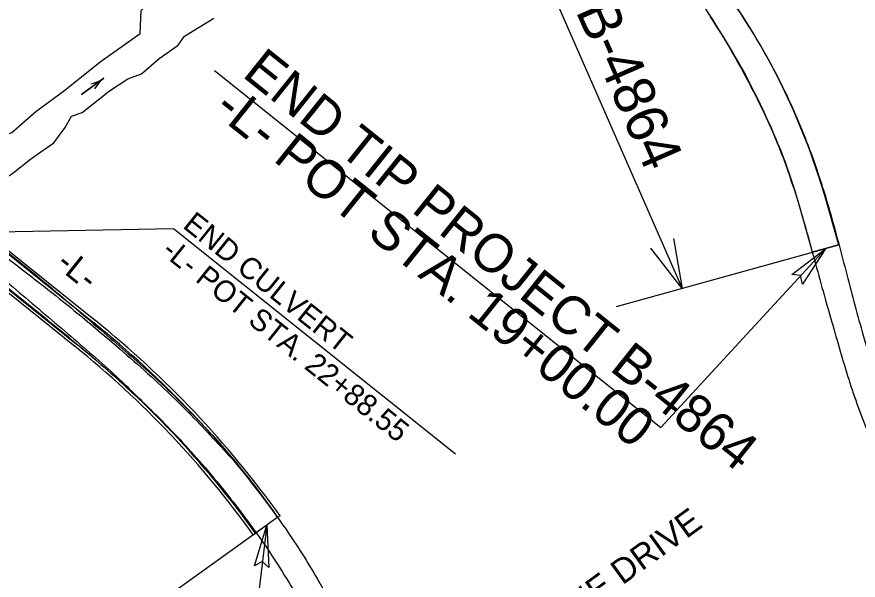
# Model space of a CAD drawing. Extents: x 1730256 to 1738218, y 910410 to 917906.
# Drawn here: x 1734907 to 1735520, y 915111 to 915523 of the extents above; entities that cross this region are included whole.
import ezdxf

# ---------------------------------------------------------------- set-up
doc = ezdxf.new("R2010")
doc.units = 0
for name, color, linetype in [('Default', 7, 'Continuous'), ('Old_Level_23', 7, 'Continuous'), ('Old_Level_3', 7, 'Continuous'), ('Old_Level_5', 7, 'Continuous'), ('Prop DSN Text', 7, 'Continuous'), ('Prop EOT', 7, 'Continuous'), ('Prop Paved Shoulder', 7, 'Continuous'), ('Prop Shade Light', 7, 'Continuous')]:
    doc.layers.add(name, color=color, linetype=linetype)

# ---------------------------------------------------------------- blocks, each defined once
blk = doc.blocks.new('EXIST HYDRO RIVER FLOW ARROW')
at = {"layer": 'Default'}
blk.add_line((0, 0), (0, 0), dxfattribs=at)
blk.add_lwpolyline([(0, 0.04575), (0.03775, 0.03), (0.07725, 0.01725), (0.118, 0.00775), (0.159, 0.0015), (0.2, 0), (-0.2, 0), (0.2, 0), (0.159, -0.0015), (0.118, -0.00775), (0.07725, -0.01725), (0.03775, -0.03), (0, -0.04575)], dxfattribs=at)

msp = doc.modelspace()

# ---------------------------------------------------------------- linework, layer by layer
at = {"layer": 'Old_Level_23'}
for p, q in [((1735146.86, 915884), (1735391.91, 915324.39)), ((1735496.49, 915353.46), (1735343.74, 915311)), ((1735088.89, 915151.46), (1734908.92, 915022.39)), ((1735088.89, 915151.46), (1735048.8, 914819.96))]:
    msp.add_line(p, q, dxfattribs=at)
at = {"layer": 'Old_Level_3'}
for points in [[(1735388.43, 915590.42), (1735416.78, 915551.19), (1735441.77, 915513.78), (1735465.3, 915471.57), (1735485.01, 915425.76), (1735499.55, 915381.43), (1735512.09, 915334.5), (1735524.18, 915290.01), (1735536.56, 915251.67), (1735553.3, 915211.16), (1735574.05, 915173.58), (1735599.55, 915136.89), (1735628.53, 915103.19), (1735661.79, 915070.16), (1735681.36, 915051.5)], [(1735374.46, 915580.41), (1735401.37, 915540.39), (1735425.26, 915502.31), (1735446.73, 915462.77), (1735465.76, 915420.2), (1735480.61, 915373.81), (1735493.26, 915327.98), (1735505.79, 915283.89), (1735518.61, 915242.74), (1735535.21, 915202.71), (1735557.35, 915162.87), (1735584.25, 915124.34), (1735613.79, 915089.74), (1735647.95, 915055.56), (1735667.73, 915036.98)], [(1734867.86, 915373.07), (1734891.7, 915356.76), (1734930.33, 915326.02), (1734970.32, 915291.99), (1735005.27, 915261.32), (1735024.06, 915243.43), (1735033.15, 915234.18), (1735042.14, 915224.81), (1735056.21, 915209.41), (1735069.65, 915193.46), (1735086.65, 915171.45), (1735102.74, 915148.77), (1735125.96, 915112.12), (1735140.95, 915084.89), (1735155.38, 915057.39), (1735158.12, 915051.66), (1735159.45, 915048.78), (1735160.89, 915045.93), (1735165.87, 915039.38), (1735172.8, 915033), (1735180.64, 915028.28), (1735182.57, 915027.8), (1735184.51, 915027.58), (1735188.38, 915027.7), (1735201.89, 915029.6), (1735214.29, 915032.53), (1735224.55, 915035.86)], [(1734867.91, 915371.3), (1734901.92, 915344.86), (1734933.09, 915320.66), (1734950.45, 915306.67), (1734981.89, 915280.2), (1735021.66, 915243.96), (1735053.56, 915211.01), (1735069.65, 915193.46)], [(1734867.91, 915371.3), (1734901.92, 915344.86), (1734933.09, 915320.66), (1734950.45, 915306.67), (1734981.89, 915280.2), (1735021.66, 915243.96), (1735053.56, 915211.01), (1735069.65, 915193.46)], [(1734858.22, 915360.67), (1734895.64, 915328.62), (1734934.22, 915297.2), (1734972.7, 915264.77), (1735005.94, 915234.2), (1735039.93, 915198.24), (1735072.41, 915158), (1735096.75, 915123.08), (1735121.96, 915080.08), (1735142.34, 915040.74), (1735163.87, 914992.3), (1735179.09, 914950.63), (1735193.56, 914895.57), (1735202.84, 914849.68), (1735206.11, 914828.68)], [(1734860.08, 915360.81), (1734901.23, 915327.52), (1734939.09, 915295.34), (1734975.42, 915263.7), (1735005.94, 915234.2)], [(1734860.08, 915360.81), (1734901.23, 915327.52), (1734939.09, 915295.34), (1734975.42, 915263.7), (1735005.94, 915234.2)]]:
    msp.add_spline(points, degree=3, dxfattribs=at)
at = {"layer": 'Old_Level_5'}
for points in [[(1734842.2, 915393.26), (1734849.26, 915399.96), (1734854.95, 915407.39), (1734872.33, 915423.08), (1734887.54, 915432.8), (1734903.06, 915438.24), (1734920.36, 915453.61), (1734941.62, 915469.24), (1734967.32, 915489.78), (1734996.6, 915510.63), (1734997.24, 915527.41), (1735007.05, 915536.59), (1735033.32, 915541.68)], [(1734864.64, 915375.65), (1734872.89, 915389.34), (1734877.09, 915389.68), (1734884.72, 915394.32), (1734889.7, 915399.34), (1734903.75, 915408.63), (1734916.66, 915418.71), (1734924.09, 915424.15), (1734933.66, 915430.75), (1734941.81, 915441.88), (1734946.57, 915450.27), (1734954.38, 915452.81), (1734974.19, 915468.68), (1734987.64, 915477.42), (1734997.51, 915481.05), (1735010.34, 915492.29), (1735024.21, 915501.95), (1735029.03, 915508.6), (1735050.33, 915521.75)]]:
    msp.add_lwpolyline(points, dxfattribs=at)
at = {"layer": 'Prop DSN Text'}
for p, q in [((1735050.76, 915483.64), (1735376.48, 915222.96)), ((1734865, 915365.22), (1735020.92, 915368.23)), ((1735020.92, 915368.23), (1735226.7, 915203.54)), ((1735376.48, 915222.96), (1735496.49, 915353.46))]:
    msp.add_line(p, q, dxfattribs=at)
msp.add_lwpolyline([(1735385.73, 915360.97), (1735391.91, 915324.39), (1735369.24, 915353.76)], dxfattribs=at)
for points in [[(1735471.97, 915334.68), (1735496.49, 915353.46), (1735479.83, 915327.46), (1735478.43, 915333.82)], [(1735079.94, 915121.9), (1735088.89, 915151.46), (1735090.54, 915120.62), (1735085.69, 915124.97)]]:
    msp.add_lwpolyline(points, close=True, dxfattribs=at)
at = {"layer": 'Prop EOT'}
for p, q in [((1734814.41, 915418.82), (1734962.69, 915299.36)), ((1734801.86, 915403.24), (1734950.14, 915283.79)), ((1735506.29, 915356.19), (1735486.95, 915350.81)), ((1735097.02, 915157.29), (1735080.77, 915145.63))]:
    msp.add_line(p, q, dxfattribs=at)
for centre, radius, start, end in [((1735006.83, 915248.06), 510, 17.87381, 34.09965), ((1735006.83, 915248.06), 490, 17.87381, 34.09965), ((1734507.86, 914734.77), 725, 35.64584, 51.14521), ((1734507.86, 914734.77), 705, 35.64584, 51.14521)]:
    msp.add_arc(centre, radius, start, end, dxfattribs=at)
for points in [[(1735492.21, 915404.59), (1735492.43, 915403.93), (1735492.64, 915403.28), (1735492.85, 915402.62), (1735493.06, 915401.96), (1735493.27, 915401.31), (1735493.48, 915400.65), (1735493.69, 915399.99), (1735493.9, 915399.34), (1735494.1, 915398.68), (1735494.31, 915398.02), (1735494.51, 915397.36), (1735494.71, 915396.7), (1735494.92, 915396.05), (1735495.12, 915395.39), (1735495.32, 915394.73), (1735495.52, 915394.07), (1735495.72, 915393.41), (1735495.92, 915392.75), (1735496.11, 915392.09), (1735496.31, 915391.43), (1735496.51, 915390.77), (1735496.7, 915390.1), (1735496.9, 915389.44), (1735497.09, 915388.78), (1735497.28, 915388.12), (1735497.47, 915387.46), (1735497.66, 915386.79), (1735497.85, 915386.13), (1735498.04, 915385.47), (1735498.23, 915384.81), (1735498.41, 915384.15), (1735498.59, 915383.5), (1735498.78, 915382.85), (1735498.96, 915382.2), (1735499.14, 915381.55), (1735499.33, 915380.9), (1735499.51, 915380.25), (1735499.69, 915379.6), (1735499.88, 915378.95), (1735500.06, 915378.3), (1735500.24, 915377.65), (1735500.43, 915377), (1735500.61, 915376.35), (1735500.79, 915375.7), (1735500.98, 915375.05), (1735501.16, 915374.4), (1735501.34, 915373.75), (1735501.53, 915373.1), (1735501.71, 915372.45), (1735501.89, 915371.8), (1735502.08, 915371.15), (1735502.26, 915370.5), (1735502.44, 915369.84), (1735502.63, 915369.19), (1735502.81, 915368.54), (1735502.99, 915367.89), (1735503.17, 915367.24), (1735503.36, 915366.59), (1735503.54, 915365.94), (1735503.72, 915365.29), (1735503.91, 915364.64), (1735504.09, 915363.99), (1735504.27, 915363.34), (1735504.46, 915362.69), (1735504.64, 915362.04), (1735504.82, 915361.39), (1735505.01, 915360.74), (1735505.19, 915360.09), (1735505.37, 915359.44), (1735505.56, 915358.79), (1735505.74, 915358.14), (1735505.92, 915357.49), (1735506.29, 915356.19)], [(1735473.18, 915398.45), (1735473.38, 915397.82), (1735473.59, 915397.19), (1735473.79, 915396.56), (1735473.99, 915395.93), (1735474.19, 915395.3), (1735474.39, 915394.67), (1735474.59, 915394.03), (1735474.79, 915393.4), (1735474.98, 915392.77), (1735475.18, 915392.14), (1735475.38, 915391.5), (1735475.57, 915390.87), (1735475.76, 915390.24), (1735475.96, 915389.61), (1735476.15, 915388.97), (1735476.34, 915388.34), (1735476.53, 915387.7), (1735476.72, 915387.07), (1735476.91, 915386.43), (1735477.1, 915385.8), (1735477.28, 915385.16), (1735477.47, 915384.53), (1735477.66, 915383.89), (1735477.84, 915383.26), (1735478.02, 915382.62), (1735478.21, 915381.98), (1735478.39, 915381.35), (1735478.57, 915380.71), (1735478.75, 915380.07), (1735478.93, 915379.44), (1735479.11, 915378.79), (1735479.29, 915378.14), (1735479.47, 915377.49), (1735479.66, 915376.84), (1735479.84, 915376.18), (1735480.02, 915375.53), (1735480.2, 915374.88), (1735480.39, 915374.23), (1735480.57, 915373.58), (1735480.75, 915372.93), (1735480.93, 915372.28), (1735481.12, 915371.63), (1735481.3, 915370.98), (1735481.48, 915370.33), (1735481.66, 915369.68), (1735481.84, 915369.03), (1735482.03, 915368.38), (1735482.21, 915367.73), (1735482.39, 915367.08), (1735482.57, 915366.43), (1735482.76, 915365.77), (1735482.94, 915365.12), (1735483.12, 915364.47), (1735483.3, 915363.82), (1735483.48, 915363.17), (1735483.67, 915362.52), (1735483.85, 915361.87), (1735484.03, 915361.22), (1735484.21, 915360.57), (1735484.4, 915359.92), (1735484.58, 915359.27), (1735484.76, 915358.62), (1735484.94, 915357.97), (1735485.12, 915357.32), (1735485.31, 915356.67), (1735485.49, 915356.01), (1735485.67, 915355.36), (1735485.85, 915354.71), (1735486.04, 915354.06), (1735486.22, 915353.41), (1735486.4, 915352.76), (1735486.58, 915352.11), (1735486.95, 915350.81)]]:
    msp.add_spline(points, degree=3, dxfattribs=at)
at = {"layer": 'Prop Paved Shoulder'}
for p, q in [((1734815.66, 915420.37), (1734963.94, 915300.92)), ((1734800.6, 915401.68), (1734948.89, 915282.23)), ((1735098.65, 915158.45), (1735097.02, 915157.29)), ((1735079.14, 915144.46), (1735080.77, 915145.63))]:
    msp.add_line(p, q, dxfattribs=at)
for radius in [727, 703]:
    msp.add_arc((1734507.86, 914734.77), radius, 35.64584, 51.14521, dxfattribs=at)
at = {"layer": 'Prop Shade Light'}
for p, q in [((1734814.41, 915418.82), (1734962.69, 915299.36)), ((1734950.14, 915283.79), (1734801.86, 915403.24)), ((1735486.95, 915350.81), (1735506.29, 915356.19)), ((1735097.02, 915157.29), (1735080.77, 915145.63))]:
    msp.add_line(p, q, dxfattribs=at)
for centre, radius, start, end in [((1735006.83, 915248.06), 510, 17.87381, 34.09965), ((1735006.83, 915248.06), 490, 17.87381, 34.09965), ((1734507.86, 914734.77), 725, 35.64584, 51.14521), ((1734507.86, 914734.77), 705, 35.64584, 51.14521)]:
    msp.add_arc(centre, radius, start, end, dxfattribs=at)
for points in [[(1735497.16, 915388.53), (1735497.14, 915388.61), (1735497.11, 915388.7), (1735497.09, 915388.78), (1735497.02, 915389), (1735496.96, 915389.22), (1735496.9, 915389.44), (1735496.83, 915389.66), (1735496.77, 915389.88), (1735496.7, 915390.1), (1735496.64, 915390.33), (1735496.57, 915390.55), (1735496.51, 915390.77), (1735496.44, 915390.99), (1735496.38, 915391.21), (1735496.31, 915391.43), (1735496.25, 915391.65), (1735496.18, 915391.87), (1735496.11, 915392.09), (1735496.05, 915392.31), (1735495.98, 915392.53), (1735495.92, 915392.75), (1735495.85, 915392.97), (1735495.79, 915393.19), (1735495.72, 915393.41), (1735495.65, 915393.63), (1735495.59, 915393.85), (1735495.52, 915394.07), (1735495.45, 915394.29), (1735495.39, 915394.51), (1735495.32, 915394.73), (1735495.25, 915394.95), (1735495.19, 915395.17), (1735495.12, 915395.39), (1735495.05, 915395.61), (1735494.98, 915395.83), (1735494.92, 915396.05), (1735494.85, 915396.27), (1735494.78, 915396.49), (1735494.71, 915396.7), (1735494.65, 915396.92), (1735494.58, 915397.14), (1735494.51, 915397.36), (1735494.44, 915397.58), (1735494.38, 915397.8), (1735494.31, 915398.02), (1735494.24, 915398.24), (1735494.17, 915398.46), (1735494.1, 915398.68), (1735494.03, 915398.9), (1735493.96, 915399.12), (1735493.9, 915399.34), (1735493.83, 915399.56), (1735493.76, 915399.78), (1735493.69, 915399.99), (1735493.62, 915400.21), (1735493.55, 915400.43), (1735493.48, 915400.65), (1735493.41, 915400.87), (1735493.34, 915401.09), (1735493.27, 915401.31), (1735493.2, 915401.53), (1735493.13, 915401.75), (1735493.06, 915401.96), (1735492.99, 915402.18), (1735492.92, 915402.4), (1735492.85, 915402.62), (1735492.78, 915402.84), (1735492.71, 915403.06), (1735492.64, 915403.28), (1735492.57, 915403.5), (1735492.5, 915403.71), (1735492.43, 915403.93), (1735492.36, 915404.15), (1735492.28, 915404.37), (1735492.21, 915404.59)], [(1735473.18, 915398.45), (1735473.25, 915398.24), (1735473.31, 915398.03), (1735473.38, 915397.82), (1735473.45, 915397.61), (1735473.52, 915397.4), (1735473.59, 915397.19), (1735473.65, 915396.98), (1735473.72, 915396.77), (1735473.79, 915396.56), (1735473.86, 915396.35), (1735473.92, 915396.14), (1735473.99, 915395.93), (1735474.06, 915395.72), (1735474.12, 915395.51), (1735474.19, 915395.3), (1735474.26, 915395.09), (1735474.32, 915394.88), (1735474.39, 915394.67), (1735474.46, 915394.46), (1735474.52, 915394.24), (1735474.59, 915394.03), (1735474.66, 915393.82), (1735474.72, 915393.61), (1735474.79, 915393.4), (1735474.85, 915393.19), (1735474.92, 915392.98), (1735474.98, 915392.77), (1735475.05, 915392.56), (1735475.12, 915392.35), (1735475.18, 915392.14), (1735475.25, 915391.93), (1735475.31, 915391.72), (1735475.38, 915391.5), (1735475.44, 915391.29), (1735475.51, 915391.08), (1735475.57, 915390.87), (1735475.64, 915390.66), (1735475.7, 915390.45), (1735475.76, 915390.24), (1735475.83, 915390.03), (1735475.89, 915389.82), (1735475.96, 915389.61), (1735476.02, 915389.39), (1735476.09, 915389.18), (1735476.15, 915388.97), (1735476.21, 915388.76), (1735476.28, 915388.55), (1735476.34, 915388.34), (1735476.4, 915388.13), (1735476.47, 915387.91), (1735476.53, 915387.7), (1735476.6, 915387.49), (1735476.66, 915387.28), (1735476.72, 915387.07), (1735476.78, 915386.86), (1735476.85, 915386.65), (1735476.91, 915386.43), (1735476.97, 915386.22), (1735477.04, 915386.01), (1735477.1, 915385.8), (1735477.16, 915385.59), (1735477.22, 915385.38), (1735477.28, 915385.16), (1735477.35, 915384.95), (1735477.41, 915384.74), (1735477.47, 915384.53), (1735477.53, 915384.32), (1735477.59, 915384.1), (1735477.66, 915383.89), (1735477.72, 915383.68), (1735477.78, 915383.47), (1735477.84, 915383.26), (1735477.9, 915383.05), (1735477.96, 915382.85), (1735478.02, 915382.64)], [(1735501.73, 915372.36), (1735501.72, 915372.39), (1735501.72, 915372.42), (1735501.71, 915372.45), (1735501.65, 915372.66), (1735501.59, 915372.88), (1735501.53, 915373.1), (1735501.46, 915373.31), (1735501.4, 915373.53), (1735501.34, 915373.75), (1735501.28, 915373.96), (1735501.22, 915374.18), (1735501.16, 915374.4), (1735501.1, 915374.61), (1735501.04, 915374.83), (1735500.98, 915375.05), (1735500.91, 915375.26), (1735500.85, 915375.48), (1735500.79, 915375.7), (1735500.73, 915375.91), (1735500.67, 915376.13), (1735500.61, 915376.35), (1735500.55, 915376.57), (1735500.49, 915376.78), (1735500.43, 915377), (1735500.37, 915377.22), (1735500.3, 915377.43), (1735500.24, 915377.65), (1735500.18, 915377.87), (1735500.12, 915378.08), (1735500.06, 915378.3), (1735500, 915378.52), (1735499.94, 915378.73), (1735499.88, 915378.95), (1735499.82, 915379.17), (1735499.75, 915379.38), (1735499.69, 915379.6), (1735499.63, 915379.82), (1735499.57, 915380.03), (1735499.51, 915380.25), (1735499.45, 915380.47), (1735499.39, 915380.68), (1735499.33, 915380.9), (1735499.27, 915381.12), (1735499.2, 915381.33), (1735499.14, 915381.55), (1735499.08, 915381.77), (1735499.02, 915381.98), (1735498.96, 915382.2), (1735498.9, 915382.42), (1735498.84, 915382.64), (1735498.78, 915382.85), (1735498.72, 915383.07), (1735498.65, 915383.29), (1735498.59, 915383.5), (1735498.53, 915383.72), (1735498.47, 915383.94), (1735498.41, 915384.15), (1735498.35, 915384.37), (1735498.29, 915384.59), (1735498.23, 915384.81), (1735498.16, 915385.03), (1735498.1, 915385.25), (1735498.04, 915385.47), (1735497.98, 915385.69), (1735497.91, 915385.91), (1735497.85, 915386.13), (1735497.79, 915386.35), (1735497.72, 915386.57), (1735497.66, 915386.79), (1735497.6, 915387.02), (1735497.53, 915387.24), (1735497.47, 915387.46), (1735497.41, 915387.68), (1735497.34, 915387.9), (1735497.28, 915388.12), (1735497.24, 915388.26), (1735497.2, 915388.39), (1735497.16, 915388.53)], [(1735478.02, 915382.64), (1735478.02, 915382.64), (1735478.02, 915382.63), (1735478.02, 915382.62), (1735478.09, 915382.41), (1735478.15, 915382.2), (1735478.21, 915381.98), (1735478.27, 915381.77), (1735478.33, 915381.56), (1735478.39, 915381.35), (1735478.45, 915381.13), (1735478.51, 915380.92), (1735478.57, 915380.71), (1735478.63, 915380.5), (1735478.69, 915380.29), (1735478.75, 915380.07), (1735478.81, 915379.86), (1735478.87, 915379.65), (1735478.93, 915379.44), (1735478.99, 915379.22), (1735479.05, 915379), (1735479.11, 915378.79), (1735479.17, 915378.57), (1735479.23, 915378.35), (1735479.29, 915378.14), (1735479.35, 915377.92), (1735479.41, 915377.7), (1735479.47, 915377.49), (1735479.54, 915377.27), (1735479.6, 915377.05), (1735479.66, 915376.84), (1735479.72, 915376.62), (1735479.78, 915376.4), (1735479.84, 915376.18), (1735479.9, 915375.97), (1735479.96, 915375.75), (1735480.02, 915375.53), (1735480.08, 915375.32), (1735480.14, 915375.1), (1735480.2, 915374.88), (1735480.26, 915374.67), (1735480.33, 915374.45), (1735480.39, 915374.23), (1735480.45, 915374.02), (1735480.51, 915373.8), (1735480.57, 915373.58), (1735480.63, 915373.37), (1735480.69, 915373.15), (1735480.75, 915372.93), (1735480.81, 915372.71), (1735480.87, 915372.5), (1735480.93, 915372.28), (1735480.99, 915372.06), (1735481.05, 915371.85), (1735481.12, 915371.63), (1735481.18, 915371.41), (1735481.24, 915371.2), (1735481.3, 915370.98), (1735481.36, 915370.76), (1735481.42, 915370.55), (1735481.48, 915370.33), (1735481.54, 915370.11), (1735481.6, 915369.9), (1735481.66, 915369.68), (1735481.72, 915369.46), (1735481.78, 915369.24), (1735481.84, 915369.03), (1735481.9, 915368.81), (1735481.97, 915368.59), (1735482.03, 915368.38), (1735482.09, 915368.16), (1735482.15, 915367.94), (1735482.21, 915367.73), (1735482.27, 915367.51), (1735482.33, 915367.29), (1735482.39, 915367.08), (1735482.42, 915366.96), (1735482.46, 915366.84), (1735482.49, 915366.73)], [(1735482.49, 915366.73), (1735482.52, 915366.63), (1735482.54, 915366.53), (1735482.57, 915366.43), (1735482.63, 915366.21), (1735482.69, 915365.99), (1735482.76, 915365.77), (1735482.82, 915365.56), (1735482.88, 915365.34), (1735482.94, 915365.12), (1735483, 915364.91), (1735483.06, 915364.69), (1735483.12, 915364.47), (1735483.18, 915364.26), (1735483.24, 915364.04), (1735483.3, 915363.82), (1735483.36, 915363.61), (1735483.42, 915363.39), (1735483.48, 915363.17), (1735483.54, 915362.96), (1735483.61, 915362.74), (1735483.67, 915362.52), (1735483.73, 915362.3), (1735483.79, 915362.09), (1735483.85, 915361.87), (1735483.91, 915361.65), (1735483.97, 915361.44), (1735484.03, 915361.22), (1735484.09, 915361), (1735484.15, 915360.79), (1735484.21, 915360.57), (1735484.27, 915360.35), (1735484.33, 915360.14), (1735484.4, 915359.92), (1735484.46, 915359.7), (1735484.52, 915359.48), (1735484.58, 915359.27), (1735484.64, 915359.05), (1735484.7, 915358.83), (1735484.76, 915358.62), (1735484.82, 915358.4), (1735484.88, 915358.18), (1735484.94, 915357.97), (1735485, 915357.75), (1735485.06, 915357.53), (1735485.12, 915357.32), (1735485.19, 915357.1), (1735485.25, 915356.88), (1735485.31, 915356.67), (1735485.37, 915356.45), (1735485.43, 915356.23), (1735485.49, 915356.01), (1735485.55, 915355.8), (1735485.61, 915355.58), (1735485.67, 915355.36), (1735485.73, 915355.15), (1735485.79, 915354.93), (1735485.85, 915354.71), (1735485.91, 915354.5), (1735485.97, 915354.28), (1735486.04, 915354.06), (1735486.1, 915353.85), (1735486.16, 915353.63), (1735486.22, 915353.41), (1735486.28, 915353.2), (1735486.34, 915352.98), (1735486.4, 915352.76), (1735486.46, 915352.54), (1735486.52, 915352.33), (1735486.58, 915352.11), (1735486.7, 915351.68), (1735486.83, 915351.24), (1735486.95, 915350.81)], [(1735506.29, 915356.19), (1735506.17, 915356.62), (1735506.05, 915357.05), (1735505.92, 915357.49), (1735505.86, 915357.7), (1735505.8, 915357.92), (1735505.74, 915358.14), (1735505.68, 915358.36), (1735505.62, 915358.57), (1735505.56, 915358.79), (1735505.5, 915359.01), (1735505.43, 915359.22), (1735505.37, 915359.44), (1735505.31, 915359.66), (1735505.25, 915359.87), (1735505.19, 915360.09), (1735505.13, 915360.31), (1735505.07, 915360.52), (1735505.01, 915360.74), (1735504.95, 915360.96), (1735504.89, 915361.17), (1735504.82, 915361.39), (1735504.76, 915361.61), (1735504.7, 915361.82), (1735504.64, 915362.04), (1735504.58, 915362.26), (1735504.52, 915362.47), (1735504.46, 915362.69), (1735504.4, 915362.91), (1735504.34, 915363.12), (1735504.27, 915363.34), (1735504.21, 915363.56), (1735504.15, 915363.77), (1735504.09, 915363.99), (1735504.03, 915364.21), (1735503.97, 915364.43), (1735503.91, 915364.64), (1735503.85, 915364.86), (1735503.79, 915365.08), (1735503.72, 915365.29), (1735503.66, 915365.51), (1735503.6, 915365.73), (1735503.54, 915365.94), (1735503.48, 915366.16), (1735503.42, 915366.38), (1735503.36, 915366.59), (1735503.3, 915366.81), (1735503.24, 915367.03), (1735503.17, 915367.24), (1735503.11, 915367.46), (1735503.05, 915367.68), (1735502.99, 915367.89), (1735502.93, 915368.11), (1735502.87, 915368.33), (1735502.81, 915368.54), (1735502.75, 915368.76), (1735502.69, 915368.98), (1735502.63, 915369.19), (1735502.56, 915369.41), (1735502.5, 915369.63), (1735502.44, 915369.84), (1735502.38, 915370.06), (1735502.32, 915370.28), (1735502.26, 915370.5), (1735502.2, 915370.71), (1735502.14, 915370.93), (1735502.08, 915371.15), (1735502.01, 915371.36), (1735501.95, 915371.58), (1735501.89, 915371.8), (1735501.84, 915371.98), (1735501.79, 915372.17), (1735501.73, 915372.36)]]:
    msp.add_open_spline(points, degree=3, dxfattribs=at)

# ---------------------------------------------------------------- block references
at = {"layer": 'Prop DSN Text', "xscale": 49.99999999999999, "yscale": 49.999999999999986, "rotation": 36.14802958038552}
msp.add_blockref('EXIST HYDRO RIVER FLOW ARROW', (1734961.97, 915471.97), dxfattribs=at)

# ---------------------------------------------------------------- texts
at = {"layer": 'Old_Level_23'}
msp.add_text('PART I            B-4864', height=30, rotation=293.64836, dxfattribs=at).set_placement((1735208.57, 915768.01))
at = {"layer": 'Prop DSN Text'}
for s, height, rotation, p in [('END TIP PROJECT B-4864', 28, 321.3297, (1735070.25, 915479.67)), ('-L- POT STA. 19+00.00', 28, 321.3297, (1735049.01, 915453.12)), ('END CULVERT', 15.75, 321.32968, (1735026.88, 915369.22)), ('-L- POT STA. 22+88.55', 15.75, 321.32968, (1735011.42, 915349.89)), ('-L-', 18, 321.32968, (1734934.33, 915340.56)), ('KEYSTONE DRIVE', 18, 35.96126, (1735236.93, 915026.59))]:
    msp.add_text(s, height=height, rotation=rotation, dxfattribs=at).set_placement(p)

doc.saveas('drawing.dxf')
